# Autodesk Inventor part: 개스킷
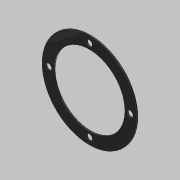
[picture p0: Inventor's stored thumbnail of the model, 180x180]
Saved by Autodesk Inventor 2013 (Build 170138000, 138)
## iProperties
Created: 2019-05
Part Number: 개스킷
Material: 고무
Document SubType Name: Modeling
Designer: mduedu
Density: 1 g/cm^3
Author: mduedu
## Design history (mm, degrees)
sketch "스케치1"
  geometry: C1 r 27 at (0, 0); C2 r 36 at (0, 0); 1 further point
  constraints: 2 centre point, 2 coincident
  dimensions: "d0" = 54 diameter of C1; "d1" = 72 diameter of C2
extrude "돌출1" new body sketch "스케치1" distance "d2" = 1; taper "d3" = 0 deg
sketch "스케치2" dims "d4" = 62
  geometry: C1 r 2.25 at (0, 31); 2 further points
  constraints: 2 vertical alignment, 1 centre point, 1 coincident, 2 other
  dimensions: "d5" = 4.5 diameter of C1
extrude "돌출2" cut sketch "스케치2" stored distance "d6" = 10; taper "d7" = 0 deg
node "솔리드1"
pattern_circular "원형 패턴1" dims angle "d9" = 360 deg
